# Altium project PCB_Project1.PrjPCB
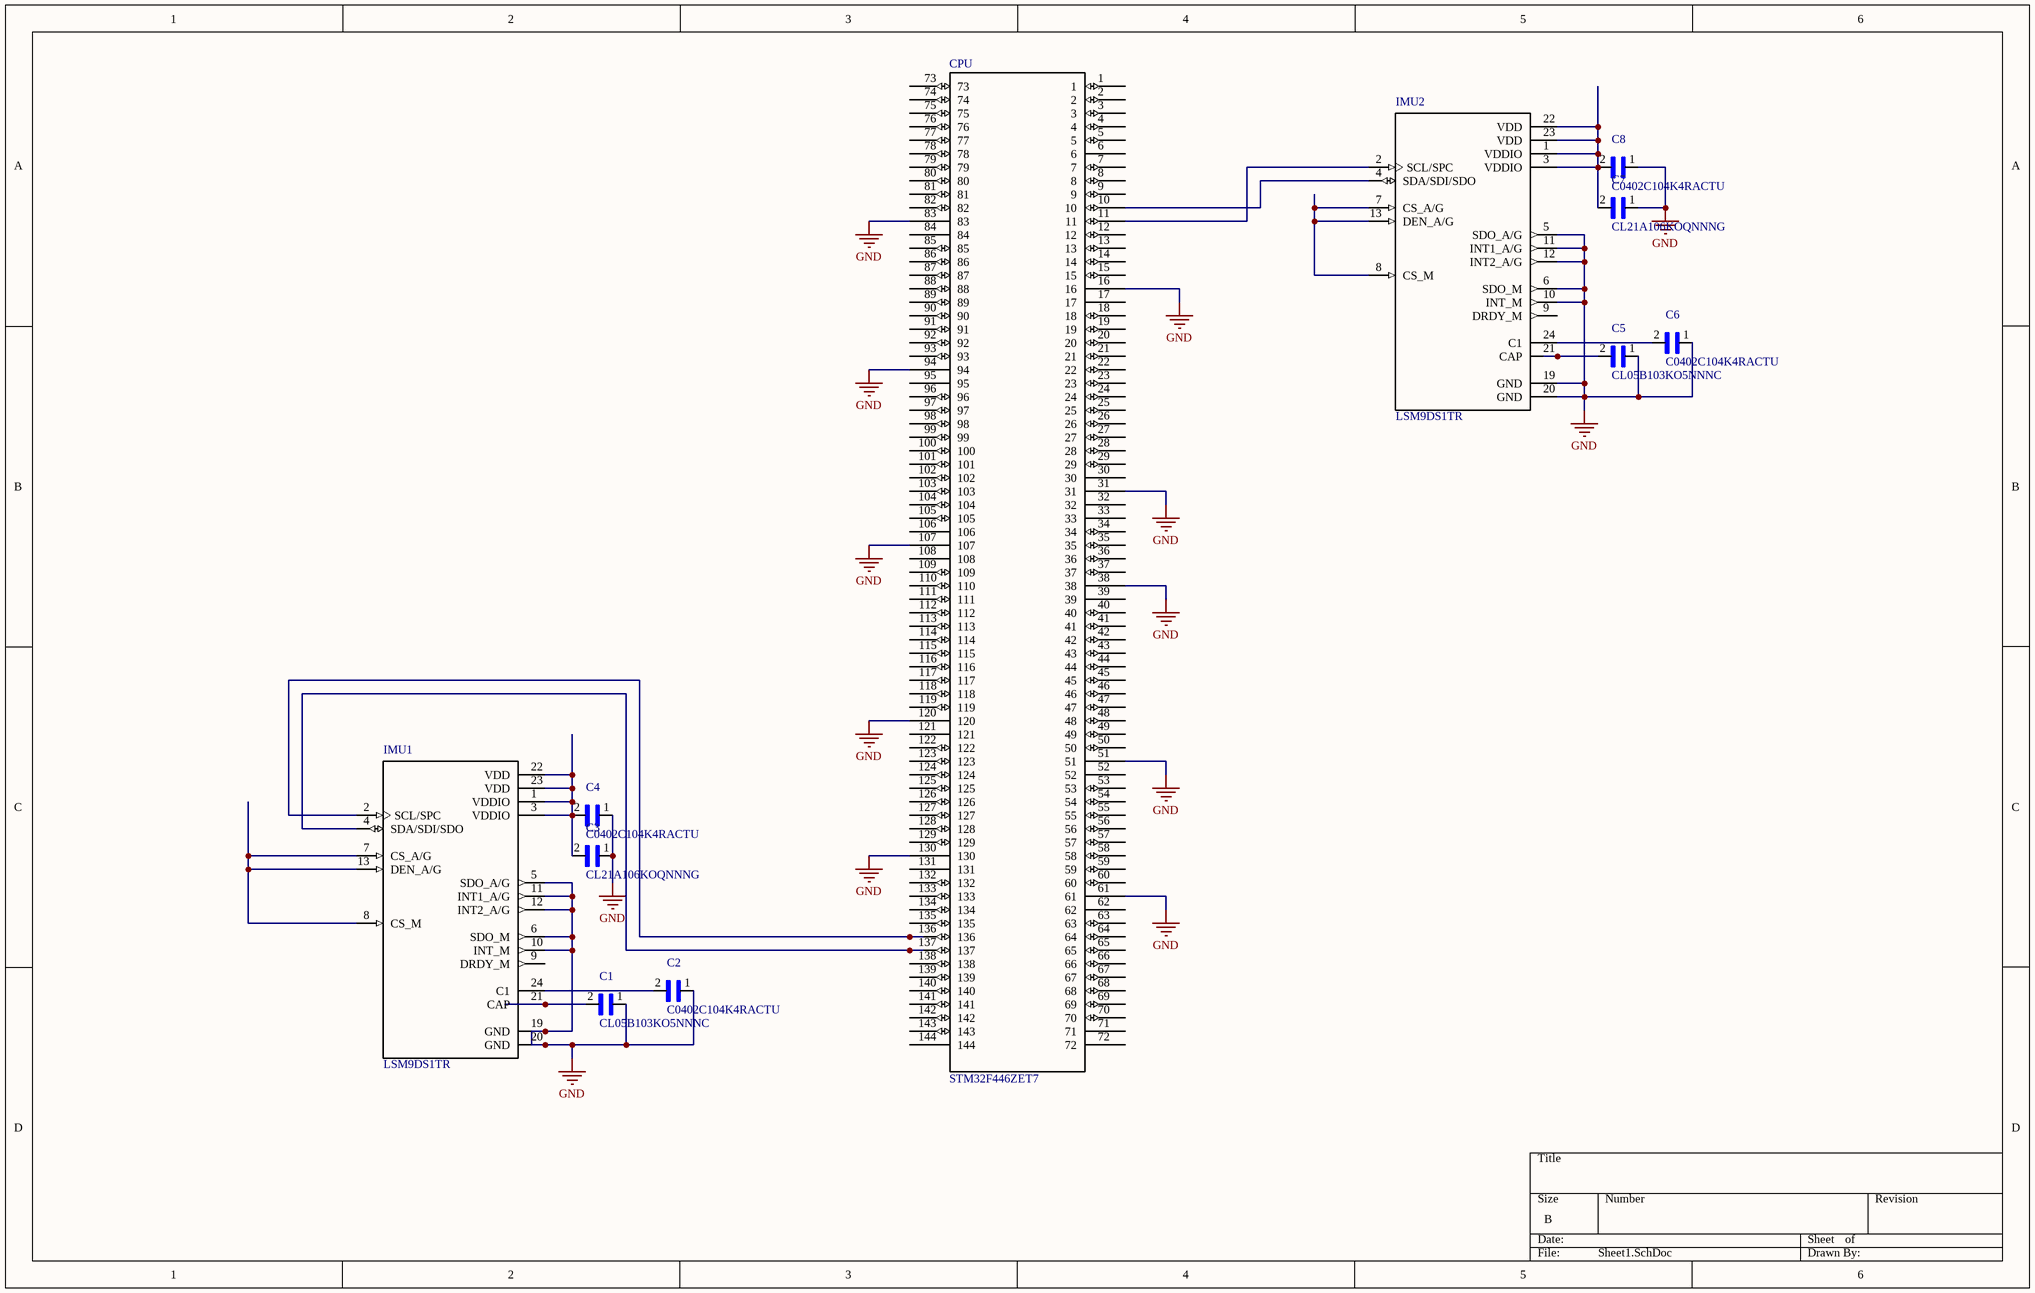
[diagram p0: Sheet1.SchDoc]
1 sheet, 11 parts. Net scope: global (net labels, ports and power ports of the same name join across sheets).

## Sheet Sheet1.SchDoc
size B

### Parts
C1  CL05B103KO5NNNC  [*CAPC1005X55N]
C2  C0402C104K4RACTU  [*CAPC1005X60]
C3  CL21A106KOQNNNG  [*CAPC2012X140N]
C4  C0402C104K4RACTU  [*CAPC1005X60]
C5  CL05B103KO5NNNC  [*CAPC1005X55N]
C6  C0402C104K4RACTU  [*CAPC1005X60]
C7  CL21A106KOQNNNG  [*CAPC2012X140N]
C8  C0402C104K4RACTU  [*CAPC1005X60]
CPU  STM32F446ZET7  [*QFP50P2200X2200X160-144N]
IMU1  LSM9DS1TR  [*PQFN43P300X350X102-24N]
IMU2  LSM9DS1TR  [*PQFN43P300X350X102-24N]

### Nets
GND: C1.1 C2.1 C3.1 C4.1 C5.1 C6.1 C7.1 C8.1 CPU.16 CPU.31 CPU.38 CPU.51 CPU.61 CPU.83 CPU.94 CPU.107 CPU.120 CPU.130 IMU1.5(SDO_A/G) IMU1.6(SDO_M) IMU1.10(INT_M) IMU1.11(INT1_A/G) IMU1.12(INT2_A/G) IMU1.19(GND) IMU1.20(GND) IMU2.5(SDO_A/G) IMU2.6(SDO_M) IMU2.10(INT_M) IMU2.11(INT1_A/G) IMU2.12(INT2_A/G) IMU2.19(GND) IMU2.20(GND)
NetC1_2: C1.2 IMU1.21(CAP)
NetC2_2: C2.2 IMU1.24(C1)
NetC3_2: C3.2 C4.2 IMU1.1(VDDIO) IMU1.3(VDDIO) IMU1.22(VDD) IMU1.23(VDD)
NetC5_2: C5.2 IMU2.21(CAP)
NetC6_2: C6.2 IMU2.24(C1)
NetC7_2: C7.2 C8.2 IMU2.1(VDDIO) IMU2.3(VDDIO) IMU2.22(VDD) IMU2.23(VDD)
NetCPU_10: CPU.10 IMU2.4(SDA/SDI/SDO)
NetCPU_11: CPU.11 IMU2.2(SCL/SPC)
NetCPU_136: CPU.136 IMU1.2(SCL/SPC)
NetCPU_137: CPU.137 IMU1.4(SDA/SDI/SDO)
NetIMU1_7: IMU1.7(CS_A/G) IMU1.8(CS_M) IMU1.13(DEN_A/G)
NetIMU2_7: IMU2.7(CS_A/G) IMU2.8(CS_M) IMU2.13(DEN_A/G)

Not connected (* = marked no-connect by the designer): CPU 1 2 3 4 5 6 7 8 9 12 13 14 15 17 18 19 20 21 22 23 24 25 26 27 28 29 30 32 33 34 35 36 37 39 40 41 42 43 44 45 46 47 48 49 50 52 53 54 55 56 57 58 59 60 62 63 64 65 66 67 68 69 70 71 72 73 74 75 76 77 78 79 80 81 82 84 85 86 87 88 89 90 91 92 93 95 96 97 98 99 100 101 102 103 104 105 106 108 109 110 111 112 113 114 115 116 117 118 119 121 122 123 124 125 126 127 128 129 131 132 133 134 135 138 139 140 141 142 143 144; IMU1 9(DRDY_M); IMU2 9(DRDY_M)

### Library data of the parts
C1 C5 = CL05B103KO5NNNC: / CL05 Series 10 nF 16 V Â±10 % Tolerance X7R SMT Multilayer Ceramic Capacitor /; MF: Samsung Electro-Mechanics
C2 C4 C6 C8 = C0402C104K4RACTU: Capacitor; Ceramic; Cap; .100uF; Tol 10%; SMT; Vol-Rtg 16V; X7R; Tape And Reel; MF: KEMET
C3 C7 = CL21A106KOQNNNG: CAP CER 10UF 16V X5R 0805; MF: Samsung Electro-Mechanics
CPU = Component_1
IMU1 IMU2 = LSM9DS1TR: / LSM9DS1 Series Â±2/Â±4/Â±8/Â±16 g 3D Digital Linear Acceleration Sensor - LGA-24 /; MF: STMicroelectronics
